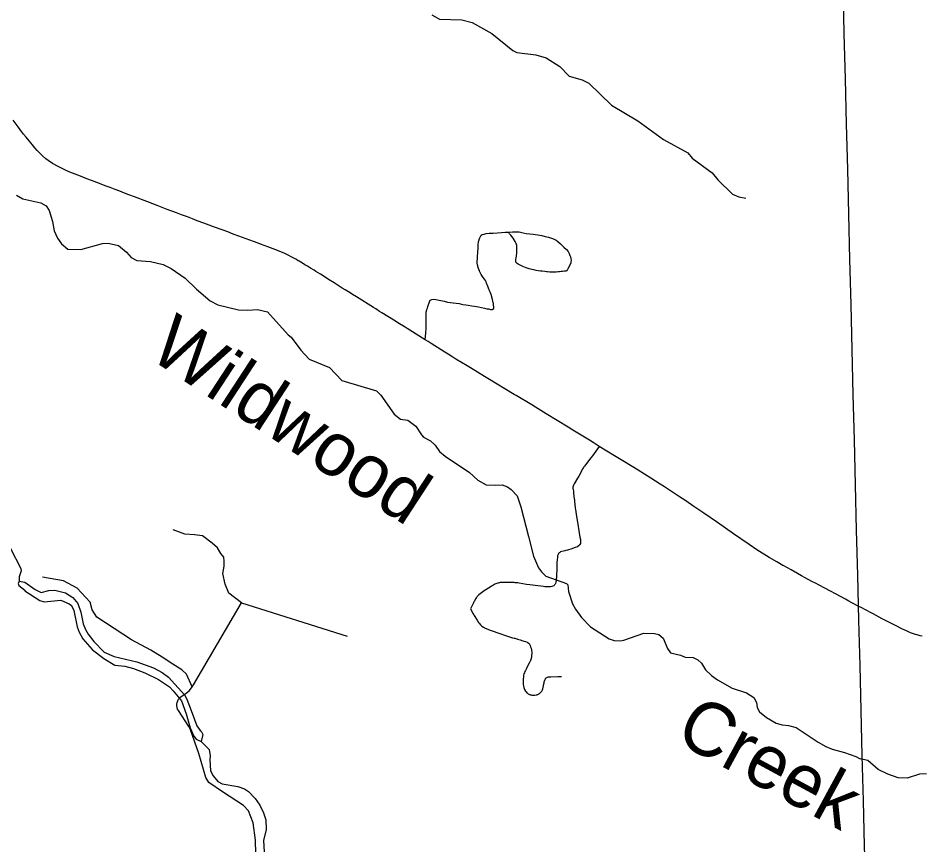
# Model space of a CAD drawing. Extents: x -19 to 366, y -4 to 359.
# Drawn here: x 140.926 to 142.275, y 192.835 to 194.069 of the extents above; entities that cross this region are included whole.
import ezdxf

# ---------------------------------------------------------------- set-up
doc = ezdxf.new("R2010")
doc.units = 0
for name, color, linetype in [('Level 31', 7, 'Continuous'), ('Level 32', 7, 'Continuous'), ('Level 33', 7, 'Continuous'), ('Level 35', 7, 'Continuous'), ('Level 60', 7, 'Continuous')]:
    doc.layers.add(name, color=color, linetype=linetype)

msp = doc.modelspace()

# ---------------------------------------------------------------- linework, layer by layer
at = {"layer": 'Level 31'}
for points in [[(141.5338, 193.589), (141.5108, 193.6034), (141.5066, 193.606), (141.5037, 193.6078), (141.4931, 193.6143), (141.4893, 193.6166), (141.4689, 193.6294), (141.4657, 193.6313), (141.4598, 193.635), (141.4564, 193.6372), (141.431, 193.653), (141.425, 193.6568), (141.4216, 193.659), (141.4142, 193.6637), (141.41, 193.6663), (141.4052, 193.6692), (141.3977, 193.674), (141.3895, 193.6791), (141.3827, 193.6834), (141.3772, 193.6868), (141.3739, 193.689), (141.3705, 193.6911), (141.3677, 193.6929), (141.3627, 193.6959), (141.3579, 193.6988), (141.3542, 193.701), (141.3505, 193.7033), (141.3455, 193.7063), (141.3442, 193.707), (141.3414, 193.7086), (141.3397, 193.7096), (141.3239, 193.7177), (141.3106, 193.7231), (141.2988, 193.7277), (141.2879, 193.7318), (141.2841, 193.7331), (141.2772, 193.7357), (141.2555, 193.7438), (141.2471, 193.7469), (141.2388, 193.7499), (141.2308, 193.7529), (141.2174, 193.7578), (141.2113, 193.76), (141.2031, 193.7632), (141.1935, 193.7667), (141.1862, 193.7695), (141.1788, 193.7723), (141.1701, 193.7756), (141.1622, 193.7785), (141.1484, 193.7836), (141.1408, 193.7866), (141.1337, 193.7893), (141.1271, 193.7918), (141.1183, 193.7952), (141.0995, 193.8024), (141.0912, 193.8056), (141.0847, 193.8081), (141.0777, 193.8107), (141.071, 193.8133), (141.0633, 193.8163), (141.056, 193.819), (141.0497, 193.8214), (141.0436, 193.8237), (141.0259, 193.8304), (141.0189, 193.8331), (141.0033, 193.8393), (140.9978, 193.8417), (140.9915, 193.8445), (140.9857, 193.8475), (140.9775, 193.8521), (140.9708, 193.8566), (140.9673, 193.8593), (140.9621, 193.8638), (140.9584, 193.8676), (140.9545, 193.8716), (140.951, 193.8757), (140.9474, 193.88), (140.9423, 193.8862), (140.9381, 193.8913), (140.9342, 193.8961), (140.9311, 193.9001), (140.9284, 193.9035), (140.9259, 193.9067), (140.9185, 193.9166)], [(141.7937, 193.4299), (141.7845, 193.4355), (141.7788, 193.439), (141.754, 193.4543), (141.747, 193.4586), (141.7145, 193.4786), (141.6984, 193.4884), (141.6927, 193.4919), (141.6696, 193.5058), (141.6668, 193.5074), (141.6271, 193.5314), (141.6224, 193.5343), (141.6014, 193.5469), (141.5965, 193.5499), (141.5797, 193.5602), (141.575, 193.5631), (141.5678, 193.5675), (141.5628, 193.5707), (141.5428, 193.5833), (141.5382, 193.5862), (141.5338, 193.589)], [(141.7937, 193.4299), (141.7835, 193.416), (141.7811, 193.4128), (141.773, 193.4024), (141.7715, 193.4004), (141.7708, 193.3996), (141.77, 193.3985), (141.7691, 193.3971), (141.7685, 193.3959), (141.763, 193.3856), (141.7612, 193.3825), (141.756, 193.3738), (141.7555, 193.3727), (141.755, 193.3718), (141.7546, 193.3703), (141.7544, 193.3689), (141.7543, 193.3671), (141.7545, 193.3654), (141.755, 193.3636), (141.7553, 193.3611), (141.7559, 193.3545), (141.7562, 193.3521), (141.7564, 193.3496), (141.7566, 193.3482), (141.7578, 193.3377), (141.758, 193.3357), (141.7586, 193.3322), (141.7592, 193.3289), (141.7622, 193.3105), (141.7628, 193.3072), (141.7648, 193.2946), (141.7654, 193.2907), (141.7655, 193.2895), (141.7657, 193.2869), (141.7655, 193.2851), (141.7645, 193.2832), (141.7639, 193.2825), (141.7613, 193.2801), (141.7578, 193.2789), (141.7511, 193.2766), (141.7478, 193.2757), (141.746, 193.2752), (141.7438, 193.2746), (141.7422, 193.2741), (141.7403, 193.2737), (141.7378, 193.2731), (141.7359, 193.2724), (141.7346, 193.2716), (141.7337, 193.2708), (141.7329, 193.2699), (141.7322, 193.2686), (141.7315, 193.2666), (141.7311, 193.2639), (141.7308, 193.2611), (141.7305, 193.2565), (141.7303, 193.2534), (141.7302, 193.2503), (141.7296, 193.2338), (141.7295, 193.2322), (141.7294, 193.2309), (141.7291, 193.2289), (141.7287, 193.2274), (141.7281, 193.2254), (141.7276, 193.2241), (141.727, 193.2231), (141.7263, 193.2222), (141.7259, 193.2219), (141.7243, 193.2211), (141.7229, 193.2206), (141.7206, 193.2201), (141.7187, 193.22), (141.7175, 193.22), (141.716, 193.2201), (141.7125, 193.2203), (141.7105, 193.2206), (141.7066, 193.221), (141.7018, 193.2217), (141.6899, 193.2233), (141.6852, 193.2239), (141.6738, 193.2258), (141.6722, 193.226), (141.6708, 193.2262), (141.6681, 193.2264), (141.6666, 193.2266), (141.6629, 193.2268), (141.6607, 193.2269), (141.6597, 193.2269), (141.6579, 193.2269), (141.6496, 193.2268), (141.6484, 193.2267), (141.6458, 193.2265), (141.6448, 193.2264), (141.6441, 193.2262), (141.6425, 193.2259), (141.6417, 193.2256), (141.6392, 193.2247), (141.6378, 193.224), (141.636, 193.223), (141.6346, 193.2222), (141.6338, 193.2218)], [(142.1056, 193.2313), (142.1009, 193.2339), (142.0957, 193.2368), (142.0897, 193.24), (142.08, 193.2455), (142.0746, 193.2485), (142.0692, 193.2515), (142.0677, 193.2523), (142.0587, 193.2574), (142.0473, 193.264), (142.0287, 193.2756), (142.0173, 193.2832), (141.9941, 193.2993), (141.9821, 193.3077), (141.97, 193.3162), (141.9498, 193.3301), (141.9348, 193.3402), (141.9227, 193.3484), (141.9118, 193.3555), (141.9, 193.3633), (141.891, 193.3693), (141.8845, 193.3735), (141.8705, 193.3826), (141.8519, 193.3943), (141.8311, 193.407), (141.8166, 193.4159), (141.7937, 193.4299)], [(141.2596, 193.1963), (141.2407, 193.2106), (141.2349, 193.224), (141.2317, 193.24), (141.2336, 193.2509), (141.2336, 193.2586), (141.233, 193.2644), (141.2285, 193.2702), (141.2234, 193.2785), (141.2157, 193.2855), (141.201, 193.2964), (141.1895, 193.2977), (141.1747, 193.299), (141.1575, 193.3054)], [(142.1662, 193.199), (142.1613, 193.2016), (142.1547, 193.2051), (142.1302, 193.2182), (142.1219, 193.2226), (142.1163, 193.2256), (142.112, 193.2279), (142.1056, 193.2313)], [(141.6338, 193.2218), (141.6323, 193.2208), (141.6243, 193.2156), (141.6205, 193.2131), (141.6199, 193.2126), (141.618, 193.2112), (141.6139, 193.2082), (141.6127, 193.2072), (141.6122, 193.2067), (141.6113, 193.2057), (141.6107, 193.205), (141.6099, 193.2039), (141.609, 193.2024), (141.6071, 193.1989), (141.6064, 193.1976), (141.6057, 193.1961), (141.6019, 193.1883), (141.6015, 193.1874)], [(142.2466, 193.1568), (142.2435, 193.1584), (142.2387, 193.1608), (142.2178, 193.1716), (142.2159, 193.1727), (142.2025, 193.1798), (142.1996, 193.1813), (142.1846, 193.1892), (142.1812, 193.191), (142.1709, 193.1965), (142.1662, 193.199)], [(141.1858, 193.071), (141.1878, 193.074), (141.2596, 193.1963), (141.4174, 193.1466)], [(141.6015, 193.1874), (141.6054, 193.1801), (141.6063, 193.1785), (141.6069, 193.1775), (141.6113, 193.1703), (141.6135, 193.1668), (141.6143, 193.1659), (141.6164, 193.1635), (141.617, 193.1629), (141.6175, 193.1623), (141.6183, 193.1617), (141.6207, 193.1599), (141.6217, 193.1593), (141.6224, 193.1589), (141.6233, 193.1585), (141.6248, 193.1578), (141.6282, 193.1564), (141.629, 193.1561), (141.648, 193.1494), (141.6506, 193.1485), (141.6582, 193.146), (141.6609, 193.1452), (141.6643, 193.1443), (141.6664, 193.1437), (141.6674, 193.1435), (141.6703, 193.1427), (141.6717, 193.1423), (141.6755, 193.1411), (141.6796, 193.1398), (141.6812, 193.1393), (141.6834, 193.1385), (141.6858, 193.1376), (141.6864, 193.1373), (141.6868, 193.1372), (141.6874, 193.1367), (141.6889, 193.1354), (141.6894, 193.1348), (141.6902, 193.1337), (141.6907, 193.1326), (141.6912, 193.1307), (141.6917, 193.1289), (141.6922, 193.1262), (141.6925, 193.1251), (141.6927, 193.1231), (141.6928, 193.1219), (141.6926, 193.1172), (141.6925, 193.1168), (141.6923, 193.1155), (141.6919, 193.1133), (141.6914, 193.1117), (141.6903, 193.1089), (141.6901, 193.1083), (141.6891, 193.1064), (141.6857, 193.1), (141.6848, 193.0981), (141.6833, 193.0952), (141.6827, 193.0938), (141.6818, 193.0918), (141.6812, 193.0902), (141.6807, 193.0882), (141.6805, 193.0869), (141.6803, 193.0855), (141.68, 193.083), (141.6799, 193.081), (141.6798, 193.0797), (141.6798, 193.078), (141.68, 193.0762), (141.6801, 193.0742), (141.6805, 193.0723), (141.6811, 193.0699), (141.6814, 193.0686), (141.6822, 193.0668), (141.6828, 193.0656), (141.6832, 193.0649), (141.6844, 193.0633), (141.6855, 193.0621), (141.6863, 193.0614), (141.6874, 193.0605), (141.6885, 193.06), (141.6893, 193.0596), (141.69, 193.0593), (141.6908, 193.0591), (141.6919, 193.0588), (141.6929, 193.0586), (141.6936, 193.0585), (141.6956, 193.0584), (141.6961, 193.0584), (141.6968, 193.0584), (141.6973, 193.0585), (141.6995, 193.0588), (141.7001, 193.059), (141.7008, 193.0592), (141.7016, 193.0595), (141.7028, 193.0601), (141.7035, 193.0605), (141.7043, 193.061), (141.7046, 193.0612), (141.705, 193.0615), (141.7066, 193.0631), (141.7069, 193.0634)], [(142.2728, 193.1473), (142.2684, 193.1484), (142.2656, 193.1492), (142.2582, 193.1518), (142.2541, 193.1535), (142.2489, 193.1558), (142.2466, 193.1568)], [(141.7069, 193.0634), (141.7073, 193.0638), (141.7078, 193.0646), (141.7089, 193.0664), (141.709, 193.0666), (141.7093, 193.0679), (141.7102, 193.0724), (141.7104, 193.0735), (141.7112, 193.077), (141.7115, 193.0782), (141.7122, 193.0808), (141.7127, 193.0818), (141.7132, 193.0827), (141.7135, 193.0834), (141.7145, 193.0843), (141.7152, 193.0849), (141.7154, 193.085), (141.7173, 193.0857), (141.7214, 193.086), (141.7317, 193.0864), (141.7334, 193.0864), (141.737, 193.0865)], [(141.2824, 192.761), (141.2805, 192.842), (141.277, 192.8681), (141.27, 192.8857), (141.2626, 192.8938), (141.2311, 192.9144), (141.2108, 192.9281), (141.2061, 192.9356), (141.1959, 192.9716), (141.1831, 193.0069), (141.1806, 193.0117), (141.1653, 193.0356), (141.1641, 193.0378), (141.1633, 193.0402), (141.1629, 193.0427), (141.163, 193.0452), (141.1634, 193.0477), (141.1643, 193.0501), (141.1655, 193.0523), (141.1671, 193.0542), (141.169, 193.0559), (141.1725, 193.0584), (141.1769, 193.0615), (141.1811, 193.0652), (141.1847, 193.0693), (141.1858, 193.071)]]:
    msp.add_lwpolyline(points, dxfattribs=at)
at = {"layer": 'Level 32'}
for points in [[(141.5338, 193.589), (141.5345, 193.5992), (141.5346, 193.6004), (141.535, 193.6056), (141.5351, 193.6077), (141.5352, 193.609), (141.5354, 193.6223), (141.5354, 193.629), (141.5354, 193.6303), (141.5358, 193.6318), (141.5364, 193.6341), (141.537, 193.6363), (141.5378, 193.6389), (141.54, 193.6459), (141.5409, 193.648), (141.5434, 193.6492), (141.5471, 193.6494), (141.5619, 193.6468), (141.5669, 193.6454), (141.5708, 193.6445), (141.5845, 193.6431), (141.5877, 193.6423), (141.5901, 193.6419), (141.5942, 193.6413), (141.5979, 193.6408), (141.6032, 193.6398), (141.6074, 193.6391), (141.6131, 193.638), (141.6223, 193.6361), (141.6257, 193.6354), (141.6281, 193.635), (141.6311, 193.6344), (141.6339, 193.634), (141.6362, 193.6358), (141.6355, 193.6434), (141.6353, 193.6444), (141.6344, 193.6491), (141.632, 193.6564), (141.631, 193.6589), (141.63, 193.6613), (141.6295, 193.6627), (141.6287, 193.6645), (141.6276, 193.6675), (141.6254, 193.6734), (141.6246, 193.6756), (141.6237, 193.6774), (141.6233, 193.678), (141.6192, 193.6836), (141.6174, 193.6865), (141.6155, 193.6903), (141.615, 193.6912), (141.6147, 193.6922), (141.614, 193.6939), (141.6125, 193.6982), (141.6121, 193.6994), (141.6117, 193.7007), (141.6114, 193.7032), (141.6113, 193.7049), (141.6113, 193.7058), (141.6117, 193.7104), (141.6119, 193.7132), (141.6122, 193.7194), (141.6126, 193.7267), (141.6129, 193.7308), (141.6134, 193.7356), (141.6137, 193.7368), (141.6147, 193.7401), (141.6161, 193.7433), (141.6175, 193.745), (141.6189, 193.746), (141.6219, 193.7469), (141.6249, 193.7475), (141.6293, 193.7481), (141.635, 193.7484), (141.6415, 193.7487), (141.6479, 193.7492), (141.6531, 193.7494), (141.6585, 193.7498)], [(141.6585, 193.7498), (141.6642, 193.7502), (141.6693, 193.7503), (141.6742, 193.7499), (141.6801, 193.7489), (141.6845, 193.7479), (141.6902, 193.7472), (141.6948, 193.7466), (141.7021, 193.7455), (141.7078, 193.7445), (141.7128, 193.7434), (141.7177, 193.7421), (141.7223, 193.7407), (141.7265, 193.7394), (141.7293, 193.7379), (141.7317, 193.7358), (141.7359, 193.732), (141.7407, 193.7274), (141.7447, 193.7236), (141.7471, 193.7207), (141.7478, 193.7197), (141.7486, 193.7179), (141.7499, 193.7147), (141.7505, 193.713), (141.7512, 193.7101), (141.7516, 193.7075), (141.7513, 193.7052), (141.7511, 193.7038), (141.7498, 193.7003), (141.7474, 193.6961), (141.7461, 193.6941), (141.7446, 193.692), (141.7435, 193.6914), (141.741, 193.6912), (141.7385, 193.691), (141.7365, 193.6908), (141.7342, 193.6905), (141.7321, 193.6902), (141.7292, 193.6899), (141.7263, 193.6898), (141.722, 193.6897), (141.7199, 193.6899), (141.7163, 193.6902), (141.715, 193.6904), (141.7122, 193.6907), (141.7083, 193.6912), (141.7058, 193.6916), (141.7026, 193.6921), (141.6996, 193.6926), (141.6959, 193.6932), (141.6927, 193.6938), (141.6892, 193.6947), (141.6847, 193.6963), (141.6818, 193.6975), (141.6796, 193.6984), (141.6765, 193.6998), (141.6747, 193.7007), (141.6725, 193.7021), (141.671, 193.7031), (141.67, 193.7039), (141.6693, 193.7048), (141.6689, 193.7065), (141.6689, 193.7077), (141.669, 193.7092), (141.6695, 193.7115), (141.6699, 193.7136), (141.6702, 193.7153), (141.6705, 193.7174), (141.6706, 193.7184), (141.6707, 193.7191), (141.6707, 193.7252), (141.6703, 193.7299), (141.6695, 193.7329), (141.6683, 193.7359), (141.665, 193.7409), (141.6614, 193.7451), (141.6598, 193.7471), (141.6589, 193.7484), (141.6585, 193.7498)], [(141.1858, 193.071), (141.1773, 193.09), (141.1705, 193.0964), (141.1567, 193.1048), (141.141, 193.1153), (141.1241, 193.1255), (141.0954, 193.1411), (141.0434, 193.1748), (141.0365, 193.186), (141.0336, 193.1973), (141.014, 193.2183), (140.9935, 193.2292), (140.9622, 193.2349)]]:
    msp.add_lwpolyline(points, dxfattribs=at)
at = {"layer": 'Level 33'}
msp.add_lwpolyline([(142.2759, 193.1466), (142.2728, 193.1473)], dxfattribs=at)
at = {"layer": 'Level 35'}
for points in [[(141.5435, 194.0741), (141.5549, 194.0674), (141.5886, 194.0667), (141.6038, 194.0627), (141.6331, 194.0464), (141.6648, 194.0206), (141.6705, 194.018), (141.6989, 194.0146), (141.7141, 194.0099), (141.7347, 193.9968), (141.7489, 193.9826), (141.7682, 193.9772), (141.7781, 193.9723), (141.8118, 193.9394), (141.8514, 193.9156), (141.8896, 193.888), (141.9258, 193.868), (141.9323, 193.8601), (141.9621, 193.8381), (141.9709, 193.8279), (141.9924, 193.8062), (142.0019, 193.8025), (142.0125, 193.8004)], [(140.9233, 193.8051), (140.9328, 193.7992), (140.9597, 193.7936), (140.9678, 193.7888), (140.9724, 193.782), (140.9772, 193.7658), (140.9797, 193.7518), (140.9848, 193.7405), (140.9907, 193.7322), (141.0002, 193.7244), (141.0195, 193.7236), (141.0519, 193.7325), (141.0602, 193.7334), (141.0757, 193.7295), (141.0876, 193.7198), (141.0949, 193.712)], [(141.0949, 193.712), (141.1033, 193.7072), (141.1234, 193.7057), (141.1423, 193.7014), (141.1542, 193.6952), (141.1752, 193.6811), (141.1925, 193.6647), (141.2128, 193.6472), (141.2243, 193.641), (141.255, 193.6335), (141.269, 193.633), (141.2833, 193.634), (141.2985, 193.6308), (141.329, 193.5965), (141.3336, 193.5927), (141.3479, 193.5736), (141.3606, 193.5602), (141.391, 193.5478), (141.4095, 193.528), (141.4608, 193.5129), (141.4673, 193.5062), (141.4875, 193.4781), (141.497, 193.4703), (141.5076, 193.469), (141.5199, 193.4601), (141.5281, 193.4469), (141.5311, 193.4436), (141.5414, 193.438), (141.5487, 193.4317), (141.5553, 193.422), (141.5634, 193.4153), (141.6001, 193.3908), (141.6124, 193.3797), (141.625, 193.3723), (141.6386, 193.3718), (141.6484, 193.3727), (141.6568, 193.3694), (141.6621, 193.3653), (141.671, 193.356), (141.6765, 193.3394), (141.6879, 193.2952), (141.6956, 193.2661), (141.7031, 193.2484), (141.7073, 193.2424), (141.7139, 193.2361), (141.7447, 193.2252), (141.7466, 193.2233), (141.7479, 193.2135), (141.7539, 193.195), (141.7582, 193.1871), (141.7671, 193.1744), (141.7806, 193.1605), (141.8085, 193.1428), (141.8157, 193.1403), (141.8248, 193.1397), (141.8304, 193.1405), (141.8601, 193.1513), (141.8763, 193.1508), (141.8828, 193.149), (141.8889, 193.1434), (141.8953, 193.128)], [(140.9143, 193.2774), (140.9299, 193.2475), (140.9307, 193.2441), (140.9277, 193.2353), (140.9277, 193.2289), (140.9262, 193.2251)], [(140.9277, 193.2289), (140.9357, 193.2274), (140.9512, 193.2161), (140.9603, 193.2119), (140.9716, 193.215), (140.9807, 193.2151), (140.9966, 193.2113), (141.0076, 193.2045), (141.0152, 193.1951), (141.0194, 193.1826), (141.0229, 193.1648), (141.0263, 193.1564), (141.0305, 193.1496), (141.0389, 193.1386), (141.0544, 193.1228), (141.0692, 193.1164), (141.1033, 193.1082), (141.1283, 193.0995), (141.1412, 193.0924), (141.1503, 193.0856), (141.1742, 193.0591), (141.178, 193.0527), (141.186, 193.0315), (141.1929, 193.0129), (141.1975, 193.0057), (141.199, 193.005), (141.2017, 192.9997), (141.1994, 192.9894)], [(140.9262, 193.2251), (140.927, 193.2224), (140.9361, 193.2153), (140.9361, 193.2141), (140.9585, 193.1998), (140.9649, 193.1979), (140.9895, 193.2003), (141.0023, 193.195), (141.0054, 193.1924), (141.0092, 193.1848), (141.0142, 193.1606), (141.0173, 193.1526), (141.0226, 193.1428), (141.0363, 193.1265), (141.0537, 193.1133), (141.0704, 193.1035), (141.0855, 193.1016), (141.0984, 193.0983), (141.1151, 193.0919), (141.1355, 193.0821), (141.1518, 193.0708), (141.1575, 193.0651), (141.1701, 193.05), (141.177, 193.0307), (141.1827, 193.0098), (141.1881, 192.9973), (141.1919, 192.9928), (141.1994, 192.9894), (141.2112, 192.9773), (141.2128, 192.9682), (141.212, 192.9625), (141.2132, 192.9454), (141.2171, 192.9379), (141.2239, 192.9296), (141.2307, 192.9262), (141.2542, 192.9221), (141.264, 192.9187), (141.2701, 192.9146), (141.28, 192.9044), (141.2868, 192.8945), (141.2922, 192.8828), (141.2956, 192.8725), (141.2964, 192.8578), (141.2923, 192.8418), (141.2932, 192.8247)], [(141.8953, 193.128), (141.8999, 193.1216), (141.9151, 193.1181), (141.9219, 193.1151), (141.9337, 193.1146), (141.9409, 193.1113), (141.9463, 193.1064), (141.9521, 193.0963), (141.9613, 193.0877), (141.9701, 193.0814), (141.9923, 193.0689), (142.0135, 193.0621), (142.0246, 193.055), (142.0285, 193.0475), (142.0294, 193.0403), (142.0329, 193.0335), (142.0433, 193.025), (142.0578, 193.0169), (142.0665, 193.0144), (142.0764, 193.0134), (142.0874, 193.0102), (142.1206, 192.9884), (142.1317, 192.9821), (142.1416, 192.9781), (142.1598, 192.9727), (142.1766, 192.9669), (142.1834, 192.9636)], [(142.2821, 192.9413), (142.2717, 192.9405), (142.2535, 192.9344), (142.2399, 192.9349), (142.2243, 192.9407), (142.2102, 192.9476), (142.1944, 192.9609), (142.1834, 192.9636)]]:
    msp.add_lwpolyline(points, dxfattribs=at)
at = {"layer": 'Level 60'}
for points in [[(146.7783, 1.697), (146.5788, 10.3131), (146.3785, 18.9294), (146.1776, 27.5458), (145.9759, 36.1624), (145.7736, 44.7791), (145.5705, 53.396), (145.3668, 62.013), (145.1624, 70.6301), (144.9572, 79.2474), (144.7514, 87.8648), (144.5449, 96.4823), (144.3377, 105.1), (144.1299, 113.7179), (143.9213, 122.3359), (143.712, 130.954), (143.5021, 139.5723), (143.2915, 148.1907), (143.0802, 156.8092), (142.8682, 165.4279), (142.6555, 174.0468), (142.4422, 182.6658), (142.2282, 191.2849), (142.0135, 199.9042), (141.7981, 208.5236), (141.582, 217.1432), (141.3653, 225.7629), (141.1479, 234.3828), (140.9298, 243.0028), (140.711, 251.623), (140.4916, 260.2433), (140.2715, 268.8638), (140.0508, 277.4844), (139.8293, 286.1051), (139.6072, 294.726), (139.3845, 303.3471), (139.161, 311.9683), (138.937, 320.5896), (138.7122, 329.2111), (138.4868, 337.8328), (138.2607, 346.4546)], [(0, 189.5162), (7.1121, 189.5206), (14.2243, 189.5339), (21.3364, 189.556), (28.4484, 189.5869), (35.5605, 189.6267), (42.6725, 189.6754), (49.7844, 189.7329), (56.8962, 189.7992), (64.0079, 189.8744), (71.1196, 189.9584), (78.2311, 190.0512), (85.3425, 190.1529), (92.4538, 190.2635), (99.5649, 190.3829), (106.6759, 190.5111), (113.7867, 190.6482), (120.8974, 190.7941), (128.0078, 190.9489), (135.1181, 191.1125), (142.2282, 191.2849), (149.338, 191.4662), (156.4476, 191.6563), (163.5569, 191.8553), (170.666, 192.0631), (177.7749, 192.2798), (184.8835, 192.5053), (191.9917, 192.7396), (199.0997, 192.9828), (206.2074, 193.2348), (213.3147, 193.4956), (220.4218, 193.7653), (227.5285, 194.0438), (234.6348, 194.3312), (241.7408, 194.6274), (248.8464, 194.9324), (255.9516, 195.2463), (263.0564, 195.569), (270.1608, 195.9005), (277.2648, 196.2409), (284.3683, 196.5901), (291.4715, 196.9481), (298.5741, 197.315), (305.6763, 197.6907), (312.7781, 198.0753), (319.8793, 198.4686), (326.9801, 198.8708), (334.0804, 199.2818), (341.1801, 199.7017)]]:
    msp.add_spline(points, degree=3, dxfattribs=at)

# ---------------------------------------------------------------- texts
at = {"layer": 'Level 35'}
for s, rotation, p in [('Wildwood', 326.851, (141.1181, 193.5636)), ('Creek', 331.5581, (141.9039, 192.9915))]:
    msp.add_text(s, height=0.08, rotation=rotation, dxfattribs=at).set_placement(p)

doc.saveas('drawing.dxf')
